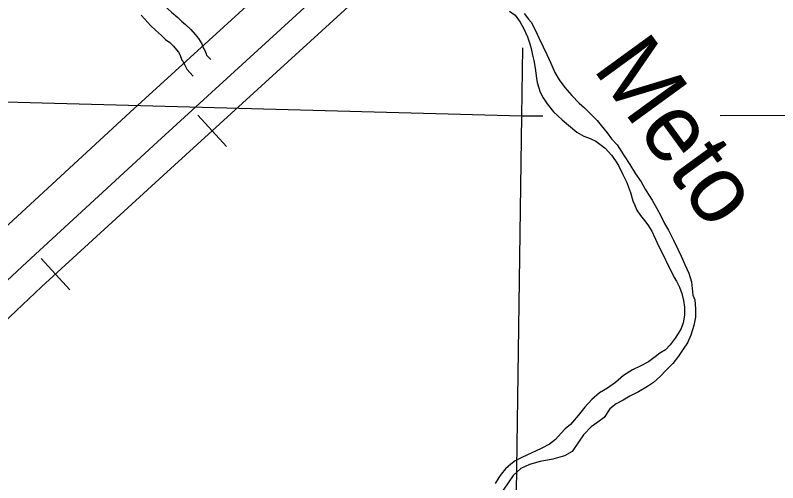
# Model space of a CAD drawing. Extents: x 1196286 to 1268366, y 2040822 to 2082115.
# Drawn here: x 1235560 to 1237337, y 2060409 to 2061499 of the extents above; entities that cross this region are included whole.
import ezdxf

# ---------------------------------------------------------------- set-up
doc = ezdxf.new("R2010")
doc.units = 0
for name, color, linetype in [('60', 7, 'Continuous'), ('62', 7, 'Continuous'), ('Level 69', 7, 'Continuous'), ('Level 81', 7, 'Continuous'), ('Level 84', 7, 'Continuous')]:
    doc.layers.add(name, color=color, linetype=linetype)

msp = doc.modelspace()

# ---------------------------------------------------------------- linework, layer by layer
at = {"layer": '60'}
for points in [[(1236711.8, 2059236.7), (1236740.6, 2061264.4), (1236742.7, 2061422.9)], [(1234992.5, 2061311.5), (1236740.6, 2061264.4), (1236789.7, 2061264.5)], [(1237202.5, 2061265.4), (1238758.5, 2061268.6)]]:
    msp.add_lwpolyline(points, dxfattribs=at)
at = {"layer": '62'}
for points in [[(1236712.2, 2061508.1), (1236724.8, 2061498.6), (1236736.6, 2061482.2), (1236744.3, 2061468.2), (1236753.5, 2061448.6), (1236759.3, 2061432), (1236762.2, 2061421.4), (1236765.4, 2061406), (1236768.6, 2061393.5), (1236771.8, 2061375.4), (1236774.9, 2061352.1), (1236776.3, 2061341.9), (1236779.2, 2061332.1), (1236783.5, 2061319.2), (1236790.5, 2061306.4), (1236799.3, 2061292.4), (1236814.5, 2061273.8), (1236834.5, 2061255.1), (1236868.7, 2061226.5), (1236885.4, 2061216.6), (1236899.6, 2061211.1), (1236912.7, 2061205), (1236934.6, 2061188.9), (1236949.4, 2061172.6), (1236958.6, 2061159.7), (1236965.6, 2061148.7), (1236975.9, 2061127.6), (1236985, 2061108.7), (1236989, 2061097.7), (1236993.8, 2061086), (1236999.2, 2061066.4), (1237003.2, 2061057.3), (1237008.7, 2061044.8), (1237017.2, 2061031.9), (1237026.4, 2061020.6), (1237034.5, 2061010.3), (1237043.8, 2060995.5), (1237056.2, 2060968.7), (1237095.4, 2060887.8), (1237100.9, 2060878.7), (1237107.9, 2060864.7), (1237113.3, 2060850), (1237116.9, 2060833.7), (1237119.4, 2060818.7), (1237119.5, 2060799.5), (1237116.3, 2060781.8), (1237111.7, 2060769.1), (1237105.2, 2060757.1), (1237098, 2060746.3), (1237086.2, 2060730.6), (1237075.2, 2060718.7), (1237062.3, 2060711), (1237051, 2060702.8), (1237035.5, 2060691.3), (1237018.2, 2060682.1), (1236998.2, 2060672.1), (1236977.5, 2060659.6), (1236958.5, 2060642.9), (1236940, 2060629.9), (1236921.6, 2060619.2), (1236903.4, 2060603.2), (1236887.1, 2060585.3), (1236871.5, 2060565.9), (1236854, 2060545.4), (1236841.9, 2060535), (1236832.5, 2060525), (1236818.8, 2060510.1), (1236805.2, 2060498.9), (1236787.1, 2060489.7), (1236772.8, 2060483.1), (1236753.6, 2060474.7), (1236738.9, 2060467.7), (1236724.9, 2060460.7), (1236715.1, 2060452.9), (1236702.2, 2060441.4), (1236692.7, 2060429.1), (1236687, 2060421.2), (1236678.6, 2060407.4)], [(1236746.2, 2061502.5), (1236755.8, 2061489.2), (1236762.1, 2061482.7), (1236772.4, 2061463.1), (1236780.4, 2061445.7), (1236790.3, 2061425.2), (1236799.1, 2061407.5), (1236808.3, 2061387.1), (1236817.4, 2061365.5), (1236827.7, 2061348.5), (1236841, 2061329.9), (1236856.9, 2061311.7), (1236874.3, 2061293.8), (1236886.9, 2061282.8), (1236900.6, 2061269.1), (1236916.2, 2061253.1), (1236925.1, 2061242.1), (1236939.1, 2061224.3), (1236949.4, 2061210.6), (1236962.4, 2061196.5), (1236979, 2061170.8), (1236991.9, 2061151.1), (1237005.5, 2061129.5), (1237018.4, 2061110.2), (1237028.3, 2061093.1), (1237036.1, 2061081), (1237044.6, 2061067.8), (1237055.2, 2061048.5), (1237063.6, 2061032.6), (1237073.2, 2061013.7), (1237082, 2060997.8), (1237094.1, 2060974.3), (1237104.4, 2060953.5), (1237112.1, 2060936.9), (1237120.1, 2060918), (1237129.6, 2060897.9), (1237136.1, 2060877.6), (1237139.2, 2060846.7), (1237143.5, 2060835.3), (1237145.2, 2060814.3), (1237145, 2060795.5), (1237141, 2060775.6), (1237134, 2060753.4), (1237126.3, 2060735.1), (1237116.8, 2060720.5), (1237105.7, 2060704.1), (1237092.1, 2060686.9), (1237076.1, 2060670.9), (1237063.3, 2060657.9), (1237047, 2060642.7), (1237033.4, 2060633.4), (1237012.3, 2060620.8), (1236992.3, 2060611.3), (1236976.8, 2060601.7), (1236960.6, 2060593.6), (1236945.9, 2060581.7), (1236932.2, 2060561.1), (1236917.8, 2060550.8), (1236902.3, 2060539.3), (1236884.5, 2060521), (1236872.3, 2060503.9), (1236857.5, 2060482.2), (1236840.1, 2060471.8), (1236813, 2060464.2), (1236783.4, 2060458.5), (1236758.6, 2060451.7), (1236738.2, 2060442.5), (1236720.4, 2060426.5), (1236697.2, 2060392.1)]]:
    msp.add_lwpolyline(points, dxfattribs=at)
at = {"layer": 'Level 69'}
for points in [[(1235893.6, 2061537.9), (1235903.6, 2061527.6), (1235915.7, 2061513.8), (1235924.6, 2061505.6), (1235938.9, 2061493.3), (1235947.9, 2061484.8), (1235957, 2061477.2), (1235969.6, 2061465.7), (1235979.5, 2061454.1), (1235987.4, 2061444.2), (1235994.8, 2061431.7), (1235998.6, 2061421.5), (1236001, 2061418.3), (1236004.8, 2061408.6), (1236006.2, 2061405.9), (1236016, 2061395.5)], [(1235853.3, 2061498.6), (1235862.3, 2061489.5), (1235875.4, 2061474.4), (1235887.2, 2061463.6), (1235901.2, 2061451.5), (1235910.7, 2061442.5), (1235920.1, 2061434.8), (1235929.1, 2061426.5), (1235936.1, 2061418.3), (1235940.9, 2061412.3), (1235943.8, 2061407.4), (1235948.7, 2061394.2), (1235951.4, 2061390.6), (1235953.5, 2061385.2), (1235960.1, 2061372.8), (1235975, 2061356.9)]]:
    msp.add_lwpolyline(points, dxfattribs=at)
at = {"layer": 'Level 81'}
for p, q in [((1236019.2, 2061229.5), (1235985.8, 2061266.1)), ((1236019.2, 2061229.5), (1236052.5, 2061193)), ((1235654, 2060895.3), (1235620.6, 2060931.8)), ((1235654, 2060895.3), (1235687.5, 2060858.8))]:
    msp.add_line(p, q, dxfattribs=at)
msp.add_lwpolyline([(1240757.7, 2065596.8), (1240486.9, 2065346.1), (1239022.5, 2063993.4), (1236837.6, 2061976.6), (1235905.3, 2061125.6), (1235621.7, 2060865.7), (1235429, 2060684.3)], dxfattribs=at)
msp.add_lwpolyline([(1240757.7, 2065596.8), (1240486.9, 2065346.1), (1239022.5, 2063993.4), (1236837.6, 2061976.6), (1235905.3, 2061125.6), (1235621.7, 2060865.7), (1235429, 2060684.3)], dxfattribs=at)
msp.add_lwpolyline([(1240757.7, 2065596.8), (1240486.9, 2065346.1), (1239022.5, 2063993.4), (1236837.6, 2061976.6), (1235905.3, 2061125.6), (1235621.7, 2060865.7), (1235429, 2060684.3)], dxfattribs=at)
at = {"layer": 'Level 84'}
for points in [[(1236329, 2061731.4), (1236151.3, 2061568.1), (1235828, 2061272.9), (1235523.6, 2060992.2), (1235350.2, 2060831.4)], [(1235413.9, 2060762.7), (1235587.2, 2060923.4), (1235891.4, 2061203.8), (1236214.7, 2061499), (1236392.4, 2061662.4)]]:
    msp.add_lwpolyline(points, dxfattribs=at)

# ---------------------------------------------------------------- texts
at = {"layer": '62'}
msp.add_text('Meto', height=158.4, rotation=306.0448, dxfattribs=at).set_placement((1236904, 2061374.7))

doc.saveas('drawing.dxf')
